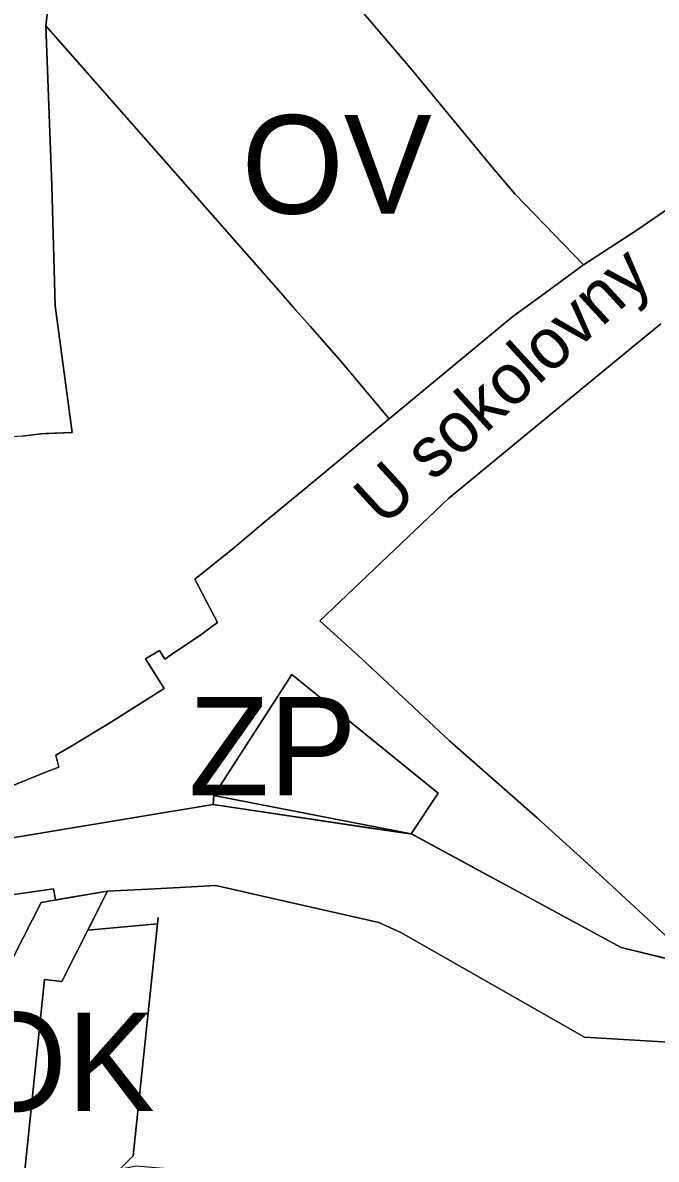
# Model space of a CAD drawing. Extents: x -555509 to -553005, y -1186756 to -1182560.
# Drawn here: x -554642.6 to -554552.4, y -1184542.3 to -1184380.7 of the extents above; entities that cross this region are included whole.
import ezdxf

# ---------------------------------------------------------------- set-up
doc = ezdxf.new("R2010")
doc.units = 0
for name, color, linetype in [('Level 15', 7, 'Continuous'), ('Level 36', 7, 'Continuous'), ('Level 52', 7, 'Continuous'), ('Level 57', 7, 'Continuous'), ('Level 59', 7, 'Continuous'), ('Level 6', 7, 'Continuous'), ('OBRYS_PLOCH', 7, 'Continuous'), ('stav_BV', 7, 'Continuous'), ('stav_DS', 7, 'Continuous'), ('stav_OK', 7, 'Continuous'), ('stav_OV', 7, 'Continuous'), ('stav_PU', 7, 'Continuous'), ('stav_ZP', 7, 'Continuous'), ('stav_ZZ', 7, 'Continuous')]:
    doc.layers.add(name, color=color, linetype=linetype)

msp = doc.modelspace()

# ---------------------------------------------------------------- linework, layer by layer
at = {"layer": 'Level 15'}
for points in [[(-554501.25, -1184380.29), (-554510.4, -1184383.49), (-554510.93, -1184383.67), (-554516.84, -1184386.71), (-554524.77, -1184390.79), (-554532.69, -1184395.37), (-554537.96, -1184398.36), (-554548.38, -1184405.51), (-554555.22, -1184410.2), (-554562.77, -1184415.14), (-554568.86, -1184419.58), (-554572.85, -1184422.48), (-554590.45, -1184437.03), (-554601.65, -1184446.29), (-554608.34, -1184451.84), (-554612.7, -1184455.49), (-554618.09, -1184459.82), (-554614.87, -1184465.98), (-554617.55, -1184467.95), (-554620.8, -1184470.08), (-554622.34, -1184471.17), (-554623.12, -1184469.96), (-554625.1, -1184471.14), (-554624.26, -1184472.46)], [(-554546.69, -1184514.53), (-554560.62, -1184501.69), (-554569.35, -1184493.77), (-554581.84, -1184482.8), (-554594.28, -1184471.19), (-554600.28, -1184465.73), (-554581.97, -1184448.29), (-554555.44, -1184426.5), (-554551.78, -1184423.5)], [(-554624.26, -1184472.46), (-554622.43, -1184475.36), (-554629.92, -1184480.1), (-554635.23, -1184483.3), (-554637.86, -1184484.85), (-554637.44, -1184486.54), (-554639.21, -1184487.21), (-554644.53, -1184489.39)], [(-554661.22, -1184499.44), (-554615.47, -1184491.83), (-554615.39, -1184490.55), (-554604.27, -1184473.37), (-554583.45, -1184490.21), (-554587.32, -1184496), (-554576.02, -1184502.11), (-554572.02, -1184504.27), (-554564.98, -1184508.08), (-554557.42, -1184512.17), (-554537.36, -1184517.08), (-554512.11, -1184515.49), (-554468.49, -1184510.58), (-554431.8, -1184526.75)], [(-554615.39, -1184490.55), (-554615.47, -1184491.83)], [(-554587.32, -1184496), (-554615.39, -1184490.55)], [(-554593.44, -1184495.14), (-554615.47, -1184491.83), (-554661.22, -1184499.44)], [(-554615.47, -1184491.83), (-554593.44, -1184495.14)], [(-554587.16, -1184496.08), (-554593.44, -1184495.14)], [(-554593.44, -1184495.14), (-554587.18, -1184496.08)], [(-554593.44, -1184495.14), (-554593.44, -1184495.14)], [(-554587.18, -1184496.08), (-554587.32, -1184496)], [(-554576.02, -1184502.11), (-554587.16, -1184496.08)], [(-554572.02, -1184504.27), (-554576.02, -1184502.11)], [(-554630.53, -1184504.15), (-554622.88, -1184503.76)], [(-554622.88, -1184503.76), (-554615.1, -1184503.37), (-554607.58, -1184505.07), (-554591.92, -1184508.62), (-554588.8, -1184510.03), (-554562.63, -1184524.9), (-554538.03, -1184526.36), (-554532.88, -1184525.38), (-554525.17, -1184524.38), (-554520.44, -1184524.39), (-554517.85, -1184525.31), (-554513.65, -1184528.36), (-554512.36, -1184531.03), (-554512.28, -1184533.93), (-554514.53, -1184541.36)], [(-554642.43, -1184545.2), (-554641.91, -1184540.17), (-554640.14, -1184523.18), (-554639.47, -1184516.74), (-554637.02, -1184517), (-554630.53, -1184504.15), (-554639.95, -1184505.76), (-554643.74, -1184513.22), (-554646.97, -1184520.1), (-554647.28, -1184523.42), (-554647.58, -1184523.38), (-554648.22, -1184527.77), (-554649.54, -1184527.64), (-554650.06, -1184533.35), (-554651.5, -1184533.21), (-554651.65, -1184534.63), (-554652.44, -1184542.42), (-554654.14, -1184542.26), (-554661.63, -1184565.18)], [(-554643.74, -1184513.22), (-554639.95, -1184505.76), (-554630.53, -1184504.15)], [(-554564.98, -1184508.08), (-554572.02, -1184504.27)], [(-554512.11, -1184515.49), (-554537.36, -1184517.08), (-554557.42, -1184512.17), (-554564.98, -1184508.08)]]:
    msp.add_lwpolyline(points, dxfattribs=at)
at = {"layer": 'Level 36'}
for points in [[(-554628.5, -1184366.61), (-554631.51, -1184366.27), (-554637.47, -1184365.6), (-554639.28, -1184381.15), (-554638.44, -1184403.84), (-554637.94, -1184420.98), (-554635.54, -1184438.95), (-554639.28, -1184439.13)], [(-554639.28, -1184439.13), (-554639.94, -1184439.16), (-554642.71, -1184439.5), (-554644.5, -1184439.63), (-554644.06, -1184444.05), (-554651.87, -1184444.95), (-554661.09, -1184446.08), (-554670.78, -1184447.34), (-554706.42, -1184451.63), (-554724.18, -1184453.83), (-554788.3, -1184460.55)]]:
    msp.add_lwpolyline(points, dxfattribs=at)
at = {"layer": 'Level 52'}
msp.add_lwpolyline([(-554637.47, -1184365.6), (-554639.28, -1184381.15), (-554638.44, -1184403.84), (-554637.94, -1184420.98), (-554635.54, -1184438.95), (-554639.94, -1184439.16), (-554642.71, -1184439.5), (-554644.5, -1184439.63), (-554644.06, -1184444.05), (-554651.87, -1184444.95), (-554661.09, -1184446.08), (-554670.78, -1184447.34), (-554706.42, -1184451.63), (-554724.18, -1184453.83), (-554788.3, -1184460.55)], dxfattribs=at)
at = {"layer": 'Level 6'}
for points in [[(-554628.5, -1184366.61), (-554631.51, -1184366.27), (-554637.47, -1184365.6), (-554639.28, -1184381.15), (-554639.14, -1184384.89)], [(-554639.14, -1184384.89), (-554638.44, -1184403.84), (-554637.94, -1184420.98), (-554635.54, -1184438.95), (-554639.94, -1184439.16), (-554642.71, -1184439.5), (-554644.5, -1184439.63), (-554644.06, -1184444.05), (-554651.87, -1184444.95), (-554661.09, -1184446.08), (-554670.78, -1184447.34), (-554706.42, -1184451.63), (-554724.18, -1184453.83), (-554788.3, -1184460.55)]]:
    msp.add_lwpolyline(points, dxfattribs=at)
at = {"layer": 'OBRYS_PLOCH'}
for p, q in [((-554639.28, -1184381.15), (-554637.47, -1184365.6)), ((-554639.28, -1184381.15), (-554607.23, -1184417.56)), ((-554638.44, -1184403.84), (-554639.28, -1184381.15)), ((-554576.01, -1184400.95), (-554572.55, -1184405.06)), ((-554637.94, -1184420.98), (-554638.44, -1184403.84)), ((-554572.55, -1184405.06), (-554562.77, -1184415.14)), ((-554568.86, -1184419.58), (-554562.77, -1184415.14)), ((-554572.85, -1184422.48), (-554568.86, -1184419.58)), ((-554635.54, -1184438.95), (-554637.94, -1184420.98)), ((-554590.45, -1184437.03), (-554572.85, -1184422.48)), ((-554615.39, -1184490.55), (-554587.32, -1184496)), ((-554615.47, -1184491.83), (-554661.22, -1184499.44)), ((-554590.39, -1184495.6), (-554615.47, -1184491.83)), ((-554587.18, -1184496.08), (-554590.39, -1184495.6)), ((-554587.18, -1184496.08), (-554587.18, -1184496.08)), ((-554587.18, -1184496.08), (-554587.18, -1184496.08)), ((-554668.82, -1184508.29), (-554638.17, -1184503.82)), ((-554638.17, -1184503.82), (-554668.82, -1184508.29)), ((-554638.17, -1184503.82), (-554637.91, -1184505.41)), ((-554637.91, -1184505.41), (-554638.17, -1184503.82)), ((-554622.88, -1184503.76), (-554630.53, -1184504.15)), ((-554630.53, -1184504.15), (-554622.88, -1184503.76)), ((-554622.88, -1184503.76), (-554615.1, -1184503.37)), ((-554615.1, -1184503.37), (-554607.58, -1184505.07)), ((-554637.91, -1184505.41), (-554630.53, -1184504.15)), ((-554630.53, -1184504.15), (-554637.91, -1184505.41)), ((-554630.53, -1184504.15), (-554633.33, -1184509.7)), ((-554607.58, -1184505.07), (-554591.92, -1184508.62)), ((-554633.33, -1184509.7), (-554623.41, -1184508.79)), ((-554623.41, -1184508.79), (-554623.31, -1184507.89)), ((-554591.92, -1184508.62), (-554588.8, -1184510.03)), ((-554588.8, -1184510.03), (-554562.63, -1184524.9)), ((-554537.36, -1184517.08), (-554557.42, -1184512.17)), ((-554562.63, -1184524.9), (-554538.03, -1184526.36))]:
    msp.add_line(p, q, dxfattribs=at)
for points in [[(-554628.5, -1184366.61), (-554631.51, -1184366.27), (-554637.47, -1184365.6), (-554639.28, -1184381.15)], [(-554576.01, -1184400.95), (-554587.15, -1184387.48), (-554606.16, -1184365.14), (-554628.5, -1184366.61)], [(-554628.5, -1184366.61), (-554606.16, -1184365.14), (-554587.15, -1184387.48), (-554576.01, -1184400.95)], [(-554639.28, -1184381.15), (-554638.44, -1184403.84), (-554637.94, -1184420.98), (-554635.54, -1184438.95), (-554639.94, -1184439.16), (-554642.71, -1184439.5), (-554644.5, -1184439.63), (-554644.06, -1184444.05), (-554651.87, -1184444.95), (-554661.09, -1184446.08), (-554670.78, -1184447.34), (-554706.42, -1184451.63), (-554724.18, -1184453.83), (-554788.3, -1184460.55)], [(-554622.43, -1184475.36), (-554625.1, -1184471.14), (-554623.12, -1184469.96), (-554622.34, -1184471.17), (-554620.8, -1184470.08), (-554617.55, -1184467.95), (-554614.87, -1184465.98), (-554618.09, -1184459.82), (-554612.7, -1184455.49), (-554608.34, -1184451.84), (-554601.65, -1184446.29), (-554590.45, -1184437.03), (-554597.32, -1184428.82), (-554601.67, -1184423.87), (-554603.74, -1184421.52), (-554605.87, -1184419.11), (-554607.23, -1184417.56), (-554639.28, -1184381.15)], [(-554562.77, -1184415.14), (-554572.55, -1184405.06), (-554576.01, -1184400.95)], [(-554562.77, -1184415.14), (-554555.22, -1184410.2), (-554548.38, -1184405.51)], [(-554607.23, -1184417.56), (-554605.87, -1184419.11), (-554603.74, -1184421.52)], [(-554603.74, -1184421.52), (-554601.67, -1184423.87), (-554597.32, -1184428.82), (-554590.45, -1184437.03)], [(-554551.78, -1184423.5), (-554555.44, -1184426.5), (-554581.97, -1184448.29), (-554600.28, -1184465.73), (-554594.28, -1184471.19), (-554581.84, -1184482.8), (-554569.35, -1184493.77), (-554560.62, -1184501.69), (-554546.69, -1184514.53)], [(-554642.71, -1184439.5), (-554639.94, -1184439.16), (-554635.54, -1184438.95)], [(-554587.32, -1184496), (-554583.45, -1184490.21), (-554604.27, -1184473.37), (-554615.39, -1184490.55)], [(-554647.72, -1184491.13), (-554644.53, -1184489.39), (-554639.21, -1184487.21), (-554637.44, -1184486.54), (-554637.86, -1184484.85), (-554635.23, -1184483.3), (-554629.92, -1184480.1), (-554622.43, -1184475.36)], [(-554572.57, -1184503.97), (-554576.02, -1184502.11), (-554587.18, -1184496.08)], [(-554589.05, -1184575.07), (-554586.8, -1184578.55), (-554558.65, -1184573.59), (-554534.86, -1184570.77), (-554523.93, -1184570.22), (-554514.53, -1184541.36), (-554512.28, -1184533.93), (-554512.36, -1184531.03), (-554513.65, -1184528.36), (-554517.85, -1184525.31), (-554520.44, -1184524.39), (-554525.17, -1184524.38), (-554532.88, -1184525.38), (-554538.03, -1184526.36), (-554562.63, -1184524.9), (-554588.8, -1184510.03), (-554591.92, -1184508.62), (-554607.58, -1184505.07), (-554615.1, -1184503.37), (-554622.88, -1184503.76)], [(-554557.42, -1184512.17), (-554572.02, -1184504.27), (-554572.57, -1184503.97)], [(-554642.43, -1184545.2), (-554641.91, -1184540.17), (-554640.14, -1184523.18), (-554639.47, -1184516.74), (-554637.02, -1184517), (-554630.53, -1184504.15)], [(-554623.31, -1184507.89), (-554626.87, -1184541.77), (-554628.76, -1184543.68), (-554626.5, -1184543.18), (-554598.31, -1184545.59)]]:
    msp.add_lwpolyline(points, dxfattribs=at)
msp.add_lwpolyline([(-554633.35, -1184546.14), (-554631.37, -1184546.32), (-554628.76, -1184543.68), (-554626.87, -1184541.77), (-554623.41, -1184508.79), (-554633.33, -1184509.7), (-554637.02, -1184517), (-554639.47, -1184516.74), (-554640.14, -1184523.18), (-554641.91, -1184540.17), (-554642.43, -1184545.2), (-554636.54, -1184545.76)], close=True, dxfattribs=at)
at = {"layer": 'stav_BV'}
for p, q in [((-554576.01, -1184400.95), (-554572.55, -1184405.06)), ((-554572.55, -1184405.06), (-554562.77, -1184415.14)), ((-554562.77, -1184415.14), (-554555.22, -1184410.2))]:
    msp.add_line(p, q, dxfattribs=at)
for points in [[(-554628.5, -1184366.61), (-554606.16, -1184365.14), (-554587.15, -1184387.48), (-554576.01, -1184400.95)], [(-554639.28, -1184381.15), (-554638.44, -1184403.84), (-554637.94, -1184420.98), (-554635.54, -1184438.95), (-554639.94, -1184439.16), (-554642.71, -1184439.5), (-554644.5, -1184439.63), (-554644.06, -1184444.05), (-554651.87, -1184444.95), (-554661.09, -1184446.08), (-554670.78, -1184447.34), (-554706.42, -1184451.63), (-554724.18, -1184453.83), (-554788.3, -1184460.55)], [(-554622.43, -1184475.36), (-554625.1, -1184471.14), (-554623.12, -1184469.96), (-554622.34, -1184471.17), (-554620.8, -1184470.08), (-554617.55, -1184467.95), (-554614.87, -1184465.98), (-554618.09, -1184459.82), (-554612.7, -1184455.49), (-554608.34, -1184451.84), (-554601.65, -1184446.29), (-554590.45, -1184437.03), (-554597.32, -1184428.82), (-554601.67, -1184423.87), (-554603.74, -1184421.52), (-554605.87, -1184419.11), (-554607.23, -1184417.56), (-554639.28, -1184381.15)], [(-554555.22, -1184410.2), (-554548.38, -1184405.51), (-554537.96, -1184398.36), (-554532.69, -1184395.37)], [(-554647.72, -1184491.13), (-554644.53, -1184489.39), (-554639.21, -1184487.21), (-554637.44, -1184486.54), (-554637.86, -1184484.85), (-554635.23, -1184483.3), (-554629.92, -1184480.1), (-554622.43, -1184475.36)]]:
    msp.add_lwpolyline(points, dxfattribs=at)
at = {"layer": 'stav_DS'}
for p, q in [((-554615.47, -1184491.83), (-554661.22, -1184499.44)), ((-554587.16, -1184496.08), (-554615.47, -1184491.83)), ((-554557.42, -1184512.17), (-554587.16, -1184496.08)), ((-554668.82, -1184508.29), (-554638.17, -1184503.82)), ((-554638.17, -1184503.82), (-554637.91, -1184505.41)), ((-554630.53, -1184504.15), (-554622.88, -1184503.76)), ((-554622.88, -1184503.76), (-554615.1, -1184503.37)), ((-554637.91, -1184505.41), (-554630.53, -1184504.15)), ((-554591.92, -1184508.62), (-554588.8, -1184510.03)), ((-554537.36, -1184517.08), (-554557.42, -1184512.17))]:
    msp.add_line(p, q, dxfattribs=at)
for points in [[(-554615.1, -1184503.37), (-554607.58, -1184505.07), (-554591.92, -1184508.62)], [(-554588.8, -1184510.03), (-554562.63, -1184524.9), (-554538.03, -1184526.36), (-554532.88, -1184525.38), (-554525.17, -1184524.38), (-554525.17, -1184524.38)]]:
    msp.add_lwpolyline(points, dxfattribs=at)
at = {"layer": 'stav_OK'}
msp.add_lwpolyline([(-554633.35, -1184546.14), (-554631.37, -1184546.32), (-554628.76, -1184543.68), (-554626.87, -1184541.77), (-554623.41, -1184508.79), (-554633.33, -1184509.7), (-554637.02, -1184517), (-554639.47, -1184516.74), (-554640.14, -1184523.18), (-554641.91, -1184540.17), (-554642.43, -1184545.2), (-554636.54, -1184545.76)], close=True, dxfattribs=at)
at = {"layer": 'stav_OV'}
for p, q in [((-554639.28, -1184381.15), (-554607.23, -1184417.56)), ((-554568.86, -1184419.58), (-554562.77, -1184415.14)), ((-554572.85, -1184422.48), (-554568.86, -1184419.58)), ((-554590.45, -1184437.03), (-554572.85, -1184422.48))]:
    msp.add_line(p, q, dxfattribs=at)
for points in [[(-554628.5, -1184366.61), (-554631.51, -1184366.27), (-554637.47, -1184365.6), (-554639.28, -1184381.15)], [(-554576.01, -1184400.95), (-554587.15, -1184387.48), (-554606.16, -1184365.14), (-554628.5, -1184366.61)], [(-554562.77, -1184415.14), (-554572.55, -1184405.06), (-554576.01, -1184400.95)], [(-554607.23, -1184417.56), (-554605.87, -1184419.11), (-554603.74, -1184421.52)], [(-554603.74, -1184421.52), (-554601.67, -1184423.87), (-554597.32, -1184428.82), (-554590.45, -1184437.03)], [(-554551.78, -1184423.5), (-554555.44, -1184426.5), (-554581.97, -1184448.29), (-554600.28, -1184465.73), (-554594.28, -1184471.19), (-554581.84, -1184482.8), (-554569.35, -1184493.77), (-554560.62, -1184501.69), (-554546.69, -1184514.53)]]:
    msp.add_lwpolyline(points, dxfattribs=at)
at = {"layer": 'stav_PU'}
for p, q in [((-554587.32, -1184496), (-554615.39, -1184490.55)), ((-554587.18, -1184496.08), (-554587.32, -1184496)), ((-554587.18, -1184496.08), (-554587.18, -1184496.08)), ((-554630.53, -1184504.15), (-554622.88, -1184503.76))]:
    msp.add_line(p, q, dxfattribs=at)
for points in [[(-554501.25, -1184380.29), (-554510.4, -1184383.49), (-554510.93, -1184383.67), (-554516.84, -1184386.71), (-554524.77, -1184390.79), (-554532.69, -1184395.37), (-554537.96, -1184398.36), (-554548.38, -1184405.51), (-554555.22, -1184410.2), (-554562.77, -1184415.14), (-554568.86, -1184419.58), (-554572.85, -1184422.48), (-554590.45, -1184437.03), (-554601.65, -1184446.29), (-554608.34, -1184451.84), (-554612.7, -1184455.49), (-554618.09, -1184459.82), (-554614.87, -1184465.98), (-554617.55, -1184467.95), (-554620.8, -1184470.08), (-554622.34, -1184471.17), (-554623.12, -1184469.96), (-554625.1, -1184471.14), (-554624.26, -1184472.46)], [(-554546.69, -1184514.53), (-554560.62, -1184501.69), (-554569.35, -1184493.77), (-554581.84, -1184482.8), (-554594.28, -1184471.19), (-554600.28, -1184465.73), (-554581.97, -1184448.29), (-554555.44, -1184426.5), (-554551.78, -1184423.5)], [(-554624.26, -1184472.46), (-554622.43, -1184475.36), (-554629.92, -1184480.1), (-554635.23, -1184483.3), (-554637.86, -1184484.85), (-554637.44, -1184486.54), (-554639.21, -1184487.21), (-554644.53, -1184489.39)], [(-554615.39, -1184490.55), (-554604.27, -1184473.37), (-554583.45, -1184490.21), (-554587.32, -1184496), (-554587.18, -1184496.08)], [(-554622.88, -1184503.76), (-554615.1, -1184503.37), (-554607.58, -1184505.07), (-554591.92, -1184508.62), (-554588.8, -1184510.03), (-554562.63, -1184524.9), (-554538.03, -1184526.36), (-554532.88, -1184525.38), (-554525.17, -1184524.38), (-554520.44, -1184524.39), (-554517.85, -1184525.31), (-554513.65, -1184528.36), (-554512.36, -1184531.03), (-554512.28, -1184533.93), (-554514.53, -1184541.36)], [(-554642.43, -1184545.2), (-554641.91, -1184540.17), (-554640.14, -1184523.18), (-554639.47, -1184516.74), (-554637.02, -1184517), (-554630.53, -1184504.15)]]:
    msp.add_lwpolyline(points, dxfattribs=at)
at = {"layer": 'stav_ZP'}
for p, q in [((-554615.39, -1184490.55), (-554587.32, -1184496)), ((-554622.88, -1184503.76), (-554630.53, -1184504.15)), ((-554630.53, -1184504.15), (-554633.33, -1184509.7)), ((-554633.33, -1184509.7), (-554623.41, -1184508.79)), ((-554623.41, -1184508.79), (-554623.31, -1184507.89))]:
    msp.add_line(p, q, dxfattribs=at)
for points in [[(-554587.32, -1184496), (-554583.45, -1184490.21), (-554604.27, -1184473.37), (-554615.39, -1184490.55)], [(-554589.05, -1184575.07), (-554586.8, -1184578.55), (-554558.65, -1184573.59), (-554534.86, -1184570.77), (-554523.93, -1184570.22), (-554514.53, -1184541.36), (-554512.28, -1184533.93), (-554512.36, -1184531.03), (-554513.65, -1184528.36), (-554517.85, -1184525.31), (-554520.44, -1184524.39), (-554525.17, -1184524.38), (-554532.88, -1184525.38), (-554538.03, -1184526.36), (-554562.63, -1184524.9), (-554588.8, -1184510.03), (-554591.92, -1184508.62), (-554607.58, -1184505.07), (-554615.1, -1184503.37), (-554622.88, -1184503.76)], [(-554623.31, -1184507.89), (-554626.87, -1184541.77), (-554628.76, -1184543.68), (-554626.5, -1184543.18), (-554598.31, -1184545.59)]]:
    msp.add_lwpolyline(points, dxfattribs=at)
at = {"layer": 'stav_ZZ'}
for p, q in [((-554639.28, -1184381.15), (-554637.47, -1184365.6)), ((-554635.54, -1184438.95), (-554637.94, -1184420.98)), ((-554642.71, -1184439.5), (-554639.94, -1184439.16)), ((-554639.94, -1184439.16), (-554635.54, -1184438.95))]:
    msp.add_line(p, q, dxfattribs=at)
msp.add_lwpolyline([(-554637.94, -1184420.98), (-554638.44, -1184403.84), (-554639.28, -1184381.15)], dxfattribs=at)

# ---------------------------------------------------------------- texts
at = {"layer": 'Level 57'}
msp.add_text('U sokolovny', height=7.1741, rotation=42.4941, dxfattribs=at).set_placement((-554591.27, -1184452.51))
at = {"layer": 'Level 59'}
for s, p in [('OV', (-554611.44, -1184407.85)), ('ZP', (-554618.97, -1184490.55)), ('OK', (-554650.84, -1184535.41))]:
    msp.add_text(s, height=14, dxfattribs=at).set_placement(p)

doc.saveas('drawing.dxf')
